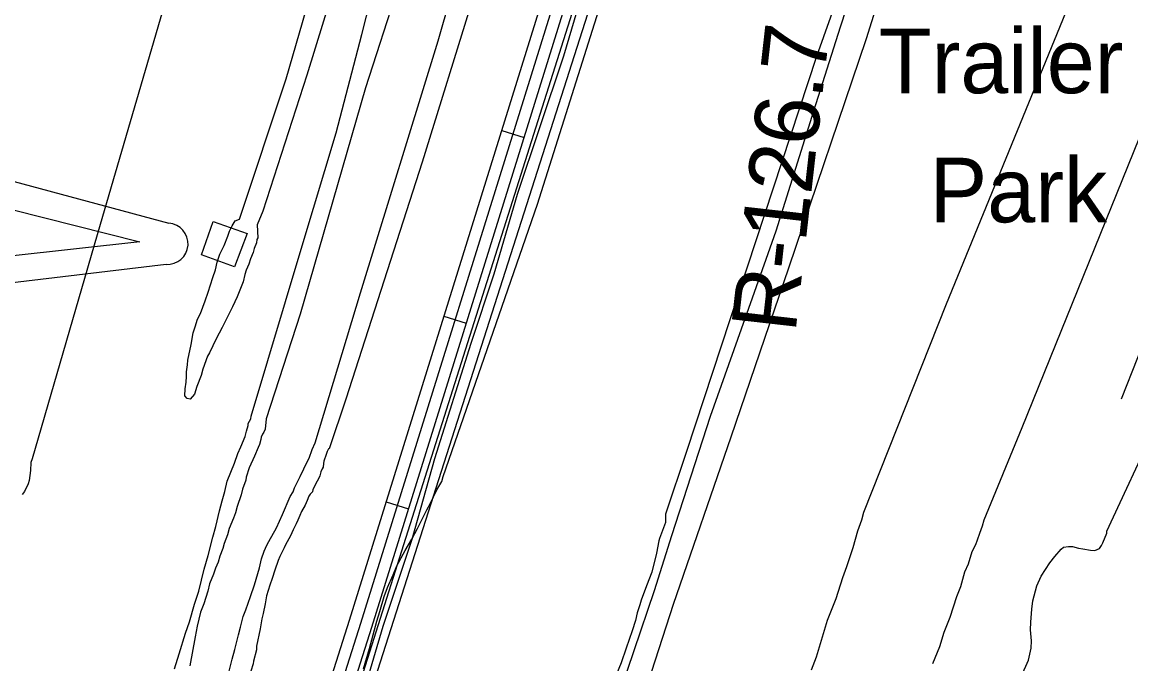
# Model space of a CAD drawing. Extents: x 3535183 to 3573198, y 534952 to 560562.
# Drawn here: x 3568179 to 3569603, y 541180 to 542005 of the extents above; entities that cross this region are included whole.
import ezdxf

# ---------------------------------------------------------------- set-up
doc = ezdxf.new("R2010")
doc.units = 0
for name, color, linetype in [('V-BLDG-IDEN', 7, 'Continuous'), ('V-BLDG-OTLN', 7, 'Continuous'), ('V-DTCH-CNTR', 7, 'Continuous'), ('V-RIVR-RANG-IDEN', 7, 'Continuous'), ('V-ROAD-CNTR', 7, 'Continuous'), ('V-SITE-VEGE', 7, 'Continuous'), ('V-TOPO-SHOR', 7, 'Continuous'), ('V-TOPO-WATR-IDEN', 7, 'Continuous'), ('V-UTIL-LINE', 7, 'Continuous')]:
    doc.layers.add(name, color=color, linetype=linetype)

msp = doc.modelspace()

# ---------------------------------------------------------------- linework, layer by layer
at = {"layer": 'V-BLDG-OTLN'}
msp.add_lwpolyline([(3568451.4, 541690.2), (3568408.9, 541705.5), (3568424.2, 541748.4), (3568467.7, 541732.8)], close=True, dxfattribs=at)
at = {"layer": 'V-DTCH-CNTR'}
msp.add_lwpolyline([(3568753.9, 540574.9), (3568774.7, 540635.9), (3568834.8, 540802.6), (3568882.4, 540940.7), (3568939.1, 541119.6), (3568991.2, 541274.1), (3569013.7, 541344.5), (3569063.2, 541498.2), (3569117.1, 541650.1), (3569147.6, 541736.1), (3569196.2, 541890.7), (3569230.4, 541998.4), (3569275.4, 542136.5), (3569290.7, 542188.6), (3569300.6, 542221.6)], dxfattribs=at)
at = {"layer": 'V-ROAD-CNTR'}
for p, q in [((3568795, 541865.3), (3568823.6, 541856.4)), ((3568720.7, 541626.6), (3568749.4, 541617.6)), ((3568646.5, 541387.8), (3568675.1, 541378.9))]:
    msp.add_line(p, q, dxfattribs=at)
for points in [[(3568389.6, 540575.4), (3568599.2, 541235.8), (3568850.8, 542044.9), (3568889.5, 542160.7), (3568909.8, 542232.1), (3568929.6, 542351.7), (3568957, 542464.1), (3569015.7, 542695.7), (3569041.4, 542833)], [(3569056.1, 542830.3), (3569030.3, 542692.5), (3568971.6, 542460.4), (3568944.3, 542348.7), (3568924.4, 542228.8), (3568903.8, 542156.2), (3568865.1, 542040.3), (3568613.5, 541231.3), (3568405.3, 540575.5)], [(3568421.1, 540575.6), (3568627.8, 541226.8), (3568879.4, 542035.7), (3568918.2, 542151.8), (3568939.1, 542225.5), (3568959, 542345.7), (3568986.1, 542456.8), (3569045, 542689.3), (3569070.9, 542827.5)], [(3570097.5, 542753.5), (3570018.5, 542568.7), (3569927.3, 542356.6), (3569863.1, 542196.1), (3569818.2, 542086.4), (3569768.6, 541944.7), (3569696.2, 541785.5), (3569591.2, 541519.8)]]:
    msp.add_lwpolyline(points, dxfattribs=at)
at = {"layer": 'V-SITE-VEGE'}
for p, q in [((3568713.4, 541980.6), (3568777.2, 542208.4)), ((3569288.1, 542208.9), (3569199.4, 541960.3)), ((3568797.9, 542164.2), (3568692.5, 541824.4)), ((3568391.6, 542131.5), (3568278.7, 541744.3)), ((3568840.8, 541770.7), (3568955.2, 542133.2)), ((3569366.6, 541642.3), (3569519.8, 542016.8)), ((3568613.5, 541656.5), (3568713.4, 541980.6)), ((3569199.4, 541960.3), (3569032.6, 541452.5)), ((3569654.5, 541955.7), (3569463.4, 541483.2)), ((3568692.5, 541824.4), (3568594.5, 541519.7)), ((3568719.5, 541420.5), (3568840.8, 541770.7)), ((3569572.7, 541350.3), (3569759.6, 541754.3)), ((3568278.7, 541744.3), (3568191.3, 541443)), ((3568555.3, 541463.9), (3568613.5, 541656.5)), ((3569260.2, 541374.6), (3569366.6, 541642.3)), ((3568594.5, 541519.7), (3568573.1, 541456)), ((3569463.4, 541483.2), (3569414.7, 541364.2)), ((3568547.3, 541444.1), (3568551.3, 541455.1)), ((3568551.3, 541455.1), (3568555.3, 541463.9)), ((3568572.2, 541455.9), (3568570.5, 541452.6)), ((3568573.1, 541456), (3568572.2, 541455.9)), ((3568191.3, 541443), (3568189.6, 541438.6)), ((3568543.3, 541435.9), (3568547.3, 541444.1)), ((3568566.5, 541440), (3568565.9, 541437.3)), ((3568569.4, 541448.8), (3568566.5, 541440)), ((3568570.5, 541452.6), (3568569.4, 541448.8)), ((3569032.6, 541452.5), (3569005.4, 541371.9)), ((3568189.5, 541428.1), (3568187.7, 541415.5)), ((3568189.6, 541438.6), (3568189.5, 541428.1)), ((3568536, 541420.6), (3568540.5, 541430.5)), ((3568540.5, 541430.5), (3568543.3, 541435.9)), ((3568562.5, 541426.3), (3568561.3, 541421.4)), ((3568564.2, 541430.2), (3568562.5, 541426.3)), ((3568565.3, 541432.3), (3568564.2, 541430.2)), ((3568565.9, 541437.3), (3568565.3, 541432.3)), ((3568186.5, 541411.1), (3568181.4, 541401.3)), ((3568187.7, 541415.5), (3568186.5, 541411.1)), ((3568528.6, 541405.9), (3568532.6, 541413.5)), ((3568532.6, 541413.5), (3568536, 541420.6)), ((3568556.2, 541411.5), (3568554.5, 541407.7)), ((3568559.6, 541417.6), (3568556.2, 541411.5)), ((3568561.3, 541421.4), (3568559.6, 541417.6)), ((3568711.6, 541403.5), (3568717.8, 541413.9)), ((3568717.8, 541413.9), (3568719.5, 541420.5)), ((3568181.4, 541401.3), (3568178.6, 541397.4)), ((3568523, 541394.9), (3568526.9, 541400.9)), ((3568526.9, 541400.9), (3568528.6, 541405.9)), ((3568548.9, 541397.9), (3568547.2, 541395.1)), ((3568551.7, 541400.6), (3568548.9, 541397.9)), ((3568552.3, 541403.9), (3568551.7, 541400.6)), ((3568554.5, 541407.7), (3568552.3, 541403.9)), ((3568703.6, 541386), (3568711.6, 541403.5)), ((3568513.3, 541371.4), (3568523, 541394.9)), ((3568542.1, 541383.6), (3568537.6, 541375.4)), ((3568544.9, 541389.7), (3568542.1, 541383.6)), ((3568547.2, 541395.1), (3568544.9, 541389.7)), ((3568698.6, 541377.8), (3568703.6, 541386)), ((3568505.3, 541354.4), (3568513.3, 541371.4)), ((3568535.3, 541370.5), (3568533, 541364.5)), ((3568537.6, 541375.4), (3568535.3, 541370.5)), ((3568686.7, 541353.8), (3568698.6, 541377.8)), ((3569005.4, 541371.9), (3569005.3, 541361.4)), ((3569257.9, 541364.7), (3569260.2, 541374.6)), ((3568495.8, 541336.9), (3568505.3, 541354.4)), ((3568530.7, 541359.6), (3568526.8, 541351.9)), ((3568533, 541364.5), (3568530.7, 541359.6)), ((3569005.3, 541361.4), (3568997.8, 541340.6)), ((3569252.7, 541350.4), (3569257.9, 541364.7)), ((3569412.4, 541356.5), (3569409, 541347.2)), ((3569414.7, 541364.2), (3569412.4, 541356.5)), ((3568523.4, 541344.3), (3568517.2, 541332.8)), ((3568526.8, 541351.9), (3568523.4, 541344.3)), ((3568670.9, 541325.3), (3568679.3, 541340.1)), ((3568679.3, 541340.1), (3568686.7, 541353.8)), ((3568997.8, 541340.6), (3568996.7, 541337.9)), ((3569246.4, 541329.1), (3569252.7, 541350.4)), ((3569409, 541347.2), (3569406.1, 541338.4)), ((3569567.6, 541335), (3569572.7, 541347.5)), ((3569572.7, 541347.5), (3569572.7, 541350.3)), ((3568489.5, 541324.3), (3568491.2, 541328.2)), ((3568491.2, 541328.2), (3568492.4, 541331.5)), ((3568492.4, 541331.5), (3568495.8, 541336.9)), ((3568515.5, 541328.9), (3568509.8, 541317.5)), ((3568517.2, 541332.8), (3568515.5, 541328.9)), ((3568996.7, 541337.9), (3568993.7, 541321.9)), ((3569242.4, 541316.4), (3569246.4, 541329.1)), ((3569403.8, 541332.4), (3569399.3, 541323.7)), ((3569406.1, 541338.4), (3569403.8, 541332.4)), ((3569505.7, 541317.6), (3569514.1, 541326.9)), ((3569514.1, 541326.9), (3569516.8, 541329.6)), ((3569516.8, 541329.6), (3569523.5, 541330.6)), ((3569523.5, 541330.6), (3569528.4, 541330.5)), ((3569528.4, 541330.5), (3569536.1, 541328.2)), ((3569536.1, 541328.2), (3569541.6, 541327.6)), ((3569541.6, 541327.6), (3569551.5, 541325.8)), ((3569551.5, 541325.8), (3569557, 541325.2)), ((3569557, 541325.2), (3569563.1, 541327.9)), ((3569563.1, 541327.9), (3569565.9, 541331.7)), ((3569565.9, 541331.7), (3569567.6, 541335)), ((3568483.7, 541302.9), (3568486.1, 541314.5)), ((3568486.1, 541314.5), (3568489.5, 541324.3)), ((3568507.5, 541312.5), (3568503.5, 541299.9)), ((3568509.8, 541317.5), (3568507.5, 541312.5)), ((3568660.1, 541305.7), (3568670.9, 541325.3)), ((3568993.7, 541321.9), (3568987.9, 541297.3)), ((3569238.4, 541304.9), (3569242.4, 541316.4)), ((3569399.3, 541323.7), (3569394.2, 541307.8)), ((3569499.5, 541309.4), (3569505.7, 541317.6)), ((3568477.4, 541281), (3568483.7, 541302.9)), ((3568503.5, 541299.9), (3568500.1, 541289.5)), ((3568655.6, 541294.2), (3568660.1, 541305.7)), ((3568987.9, 541297.3), (3568981.1, 541279.7)), ((3569233.2, 541290.7), (3569238.4, 541304.9)), ((3569389.6, 541297.4), (3569384.4, 541278.7)), ((3569394.2, 541307.8), (3569389.6, 541297.4)), ((3569488.3, 541292.5), (3569499.5, 541309.4)), ((3568500.1, 541289.5), (3568496.7, 541280.7)), ((3568648.2, 541277.7), (3568655.6, 541294.2)), ((3569224.6, 541263.8), (3569233.2, 541290.7)), ((3569482.6, 541279.9), (3569488.3, 541292.5)), ((3568472.2, 541266.2), (3568477.4, 541281)), ((3568496.7, 541280.7), (3568492.6, 541267)), ((3568643.7, 541266.2), (3568648.2, 541277.7)), ((3568981.1, 541279.7), (3568974.2, 541261.6)), ((3569384.4, 541278.7), (3569379.3, 541265.6)), ((3569477.4, 541260.7), (3569482.6, 541279.9)), ((3568466, 541249.2), (3568472.2, 541266.2)), ((3568490.8, 541256.6), (3568488.5, 541244.5)), ((3568492.6, 541267), (3568490.8, 541256.6)), ((3568638.4, 541247), (3568643.7, 541266.2)), ((3568972.5, 541255.6), (3568969, 541245.2)), ((3568974.2, 541261.6), (3568972.5, 541255.6)), ((3569213.8, 541235.9), (3569224.6, 541263.8)), ((3569379.3, 541265.6), (3569370.7, 541239.3)), ((3569476.1, 541249.7), (3569477.4, 541260.7)), ((3568459, 541226.7), (3568462.5, 541240.4)), ((3568462.5, 541240.4), (3568466, 541249.2)), ((3568488.5, 541244.5), (3568486.7, 541237.4)), ((3568634.4, 541234.4), (3568638.4, 541247)), ((3568969, 541245.2), (3568966.7, 541235.3)), ((3569474.8, 541233.2), (3569476.1, 541249.7)), ((3568456.7, 541216.8), (3568459, 541226.7)), ((3568486.7, 541237.4), (3568484.3, 541224.7)), ((3568625.1, 541199.3), (3568634.4, 541234.4)), ((3568966.7, 541235.3), (3568962.7, 541222.2)), ((3569199.4, 541188.7), (3569213.8, 541235.9)), ((3569370.7, 541239.3), (3569363.3, 541220.1)), ((3569474.7, 541223.3), (3569474.8, 541233.2)), ((3568452.1, 541198.2), (3568456.7, 541216.8)), ((3568484.3, 541224.7), (3568479.6, 541202.2)), ((3568962.7, 541222.2), (3568954.7, 541199.7)), ((3569363.3, 541220.1), (3569357.5, 541201.4)), ((3569475.6, 541209), (3569474.7, 541223.3)), ((3568448.6, 541185.6), (3568452.1, 541198.2)), ((3568479.6, 541197.8), (3568476.1, 541183)), ((3568479.6, 541202.2), (3568479.6, 541197.8)), ((3568617.1, 541173), (3568625.1, 541199.3)), ((3568954.7, 541199.7), (3568948.4, 541181)), ((3569357.5, 541201.4), (3569348.4, 541179.5)), ((3569472, 541184.3), (3569475.5, 541199.6)), ((3569475.5, 541199.6), (3569475.6, 541209)), ((3568444.5, 541170.2), (3568448.6, 541185.6)), ((3569193.1, 541171.7), (3569199.4, 541188.7)), ((3569462.9, 541164), (3569472, 541184.3)), ((3568475.5, 541179.7), (3568472.6, 541170.4)), ((3568476.1, 541183), (3568475.5, 541179.7)), ((3568948.4, 541181), (3568941.5, 541164.1))]:
    msp.add_line(p, q, dxfattribs=at)
for points in [[(3568662.4, 542318.5), (3568544.3, 541936.6), (3568488, 541761.5), (3568480.8, 541744), (3568481.4, 541727.3), (3568480.3, 541725.1), (3568479.7, 541720.7), (3568476.8, 541713.6), (3568475.6, 541708.6), (3568472.2, 541700.4), (3568469.9, 541693.3), (3568466.5, 541685.6), (3568464.8, 541680.1), (3568462.5, 541670.8), (3568455.1, 541651.6), (3568448.8, 541638.5), (3568435.8, 541612.2), (3568427.9, 541597.5), (3568419.4, 541579.4), (3568416.6, 541575.1), (3568410.9, 541558.6), (3568408.6, 541550.4), (3568402.9, 541536.2), (3568400, 541526.3), (3568394.4, 541519.7), (3568390.5, 541520.9), (3568387.8, 541524.2), (3568388, 541533), (3568389.2, 541541.8), (3568389.8, 541549), (3568389.9, 541555), (3568391.1, 541563.8), (3568391.7, 541569.9), (3568395.9, 541590.2), (3568398.3, 541605), (3568401.1, 541612.7), (3568404, 541622.6), (3568408, 541630.2), (3568413.7, 541646.1), (3568417.7, 541657.6), (3568423.5, 541676.3), (3568426.9, 541686.2), (3568429.2, 541696), (3568432.7, 541706.4), (3568438.3, 541717.4), (3568442.9, 541729.4), (3568445.2, 541736), (3568448.6, 541742.6), (3568452.5, 541749.1), (3568458, 541751.3), (3568517.9, 541931.6), (3568603.5, 542227.7)], [(3568703.1, 542177.5), (3568619.7, 541920.1), (3568535.9, 541629.2), (3568492.3, 541494.4)], [(3568451.3, 541437.8), (3568455.9, 541449.9), (3568459.8, 541458.6), (3568465, 541471.8), (3568466.7, 541478.9), (3568469, 541486), (3568469, 541488.8), (3568472.4, 541494.8), (3568473, 541498.1), (3568538.5, 541717.1), (3568582.2, 541862.4), (3568615.1, 541988.6), (3568651.7, 542132.3)], [(3568492.3, 541494.4), (3568491, 541481.3), (3568489.3, 541477.5), (3568487.6, 541474.8), (3568485.9, 541470.9), (3568485.3, 541468.2), (3568483.6, 541461.6), (3568481.8, 541457.8), (3568477.3, 541446.8), (3568470.5, 541431.5), (3568466.5, 541419.4), (3568465.9, 541415.6), (3568461.9, 541404.1), (3568460.1, 541396.9), (3568455, 541382.1), (3568452.6, 541373.9), (3568450.4, 541366.8), (3568444.7, 541353.7), (3568442.4, 541345.4), (3568438.4, 541334.5), (3568436.6, 541327.9), (3568432.6, 541318), (3568430.3, 541310.3), (3568426.9, 541302.7), (3568424.6, 541295), (3568419.5, 541282.4), (3568417.2, 541273.1), (3568412, 541256.6), (3568408, 541246.2), (3568403.4, 541228.1), (3568401, 541214.4), (3568393.9, 541177)], [(3568374.5, 541173.4), (3568380.3, 541192.6), (3568388.4, 541218.9), (3568393.5, 541233.7), (3568399.9, 541256.2), (3568405.6, 541273.2), (3568412.6, 541301.2), (3568417.8, 541318.8), (3568423.6, 541342.4), (3568427.6, 541356.1), (3568432.3, 541376.4), (3568435.8, 541389), (3568439.2, 541401.1), (3568442.2, 541414.3), (3568451.3, 541437.8)]]:
    msp.add_lwpolyline(points, dxfattribs=at)
at = {"layer": 'V-TOPO-SHOR'}
for points in [[(3569085.9, 542799.5), (3569074.1, 542770.8), (3569058.3, 542718.3), (3569042.6, 542631.3), (3569015.9, 542534.4), (3568987.8, 542428), (3568956.7, 542278), (3568932.1, 542169.8), (3568903.9, 542061.1), (3568874.2, 541960.8), (3568843.6, 541868.8), (3568814.8, 541782.8), (3568784.6, 541680.7), (3568755.4, 541591.3), (3568708.6, 541443.2), (3568679.6, 541339.4), (3568642.3, 541227.8), (3568604, 541098.3), (3568559, 540960.3), (3568523.8, 540846), (3568475.7, 540700.2), (3568437, 540573.8), (3568436.6, 540572.5)], [(3569338.7, 542224.1), (3569263.4, 541983.3), (3569163.7, 541688.3), (3569089.5, 541471.2), (3569015.2, 541255.8), (3568930.9, 540994.9), (3568886.5, 540869.7), (3568826.7, 540689.3), (3568787.3, 540575.1)]]:
    msp.add_lwpolyline(points, dxfattribs=at)
at = {"layer": 'V-TOPO-WATR-IDEN'}
for points in [[(3567122.9, 541831.8), (3567425.8, 541871.8), (3567435.7, 542016.1), (3568072.7, 541972.3), (3568062.8, 541827.9), (3568367.1, 541746.1)], [(3568083.6, 541784.1), (3568329.8, 541722.1), (3568077.4, 541694.3)], [(3568363.5, 541693.2), (3568040.2, 541654.6), (3567837.3, 541668.6), (3567826.6, 541513.6), (3567638, 541526.6), (3567648.7, 541681.6), (3567424.4, 541697), (3567119.3, 541778.9)]]:
    msp.add_lwpolyline(points, dxfattribs=at)
msp.add_arc((3568365.3, 541719.6), 26.5, 266.0596, 86.0596, dxfattribs=at)
at = {"layer": 'V-UTIL-LINE'}
for points in [[(3570939.4, 552291.6), (3570849.1, 552211.5), (3569548.9, 551126.6), (3568625, 550412.5), (3568598.6, 550392.1), (3568238.5, 550116), (3568124.2, 549911.1), (3567700.4, 549152.4), (3566983.7, 547869), (3567517.4, 547561.1), (3569316.2, 545945.9), (3569331.4, 545867.9), (3569368.9, 543127), (3569352.8, 543013.2), (3569354.5, 542782.5), (3569354.6, 542779), (3569354.6, 542777.6), (3569352.7, 542706.1), (3569074.9, 542711.5), (3568970.1, 542218.9), (3568443.7, 540572.5)], [(3570939.9, 552222.4), (3570535.3, 551886.4), (3568260.8, 550054.4), (3568175.1, 549886.6), (3567095.5, 547774.9), (3567514.7, 547600.4), (3567916.8, 547434.9), (3567543.9, 546342.9), (3567623.7, 546336.5), (3568423.1, 546277.7), (3568456, 546292.7), (3568479.7, 546273.4), (3569276.9, 546236), (3569276.6, 546213.5), (3569327.2, 542794.5), (3569326.5, 542748.2), (3569070.1, 542749.3), (3568961.5, 542258.4), (3568428.1, 540572.4)]]:
    msp.add_lwpolyline(points, dxfattribs=at)

# ---------------------------------------------------------------- texts
at = {"layer": 'V-BLDG-IDEN'}
for s, p in [('Trailer', (3569279.6, 541913.2)), ('Park', (3569344.8, 541747.2))]:
    msp.add_text(s, height=83, dxfattribs=at).set_placement(p)
at = {"layer": 'V-RIVR-RANG-IDEN'}
msp.add_text('R-126.7', height=83, rotation=83.5369, dxfattribs=at).set_placement((3569172.3, 541604.1))

doc.saveas('drawing.dxf')
